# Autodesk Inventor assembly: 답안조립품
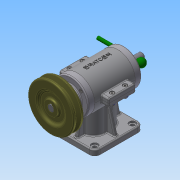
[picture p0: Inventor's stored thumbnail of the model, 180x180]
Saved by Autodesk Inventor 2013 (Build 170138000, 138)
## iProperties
Created: 2015-12
Part Number: 답안조립품
Document SubType Name: Assembly
Designer: Administrator
Mass: 1960.55 g
Surface Area: 1487.03 cm^2
Volume: 472.445 cm^3
Density: 4.14979 g/cm^3
Author: Administrator
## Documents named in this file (19)
- C:\Users\Administrator\Desktop\351208V1024\답안조립품.iam
- C:\Users\Administrator\Desktop\351208V1024\본체.ipt
- C:\Users\Administrator\Desktop\351208V1024\V-벨트풀리.ipt
- C:\Users\Administrator\Desktop\351208V1024\너트 M4.ipt
- C:\Users\Administrator\Desktop\351208V1024\뒤커버.ipt
- C:\Users\Administrator\Desktop\351208V1024\레바.ipt
- C:\Users\Administrator\Desktop\351208V1024\멈춤나사 M3x8.ipt
- C:\Users\Administrator\Desktop\351208V1024\베어링 6201.ipt
- C:\Users\Administrator\Desktop\351208V1024\베어링 6202.ipt
- C:\Users\Administrator\Desktop\351208V1024\본체커버.ipt
- C:\Users\Administrator\Desktop\351208V1024\볼트 M3x0.5x8.ipt
- C:\Users\Administrator\Desktop\351208V1024\볼트 M4 x 16.ipt
- C:\Users\Administrator\Desktop\351208V1024\스프링.ipt
- C:\Users\Administrator\Desktop\351208V1024\슬라이드.ipt
- C:\Users\Administrator\Desktop\351208V1024\앞커버.ipt
- C:\Users\Administrator\Desktop\351208V1024\오일실 12 22 7.ipt
- C:\Users\Administrator\Desktop\351208V1024\와셔 ST 4-100.ipt
- C:\Users\Administrator\Desktop\351208V1024\키 4 x 4 x 18.ipt
- C:\Users\Administrator\Desktop\351208V1024\편심축.ipt
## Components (13 placed, 4 different names)
1. V-벨트풀리:1 — 플러쉬:1
2. ISO 4032 M4:1
3. ISO 4762 M4 x 16:1
4. ISO 7091 ST 4 - 100 HV:1
5. ISO 4762 M4 x 16:2
6. ISO 4762 M4 x 16:3
7. ISO 4762 M4 x 16:4
8. ISO 7091 ST 4 - 100 HV:2
9. ISO 7091 ST 4 - 100 HV:3
10. ISO 7091 ST 4 - 100 HV:4
11. ISO 4032 M4:2
12. ISO 4032 M4:3
13. ISO 4032 M4:4
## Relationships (1: Flush 1)
- 플러쉬:1 [Flush]: V-벨트풀리:1
